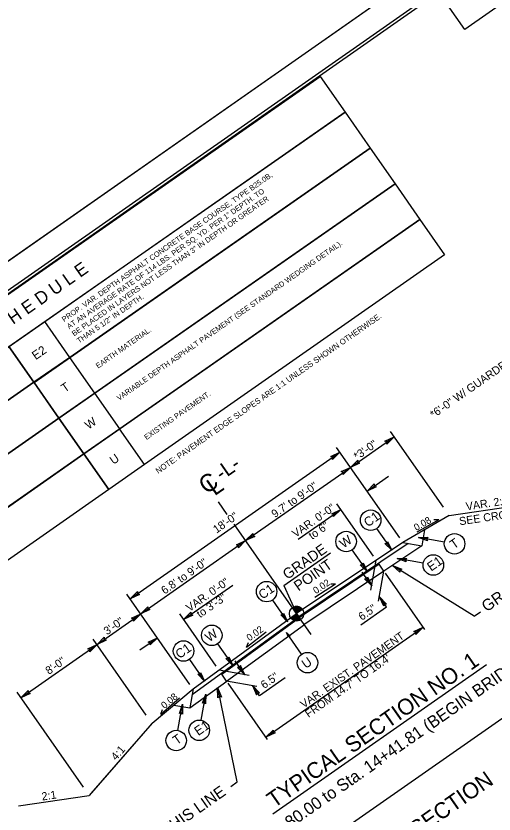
# Model space of a CAD drawing. Extents: x 1033697 to 1037131, y 657437 to 660507.
# Drawn here: x 1035520 to 1035969, y 659179 to 659927 of the extents above; entities that cross this region are included whole.
import ezdxf

# ---------------------------------------------------------------- set-up
doc = ezdxf.new("R2010")
doc.units = 0
for name, color, linetype in [('Default', 7, 'Continuous'), ('Prop Pavement Schedule Description CELL', 7, 'Continuous'), ('Sheet Cutting Line CELL', 7, 'Continuous'), ('Sheet Plot Border Inside CELL', 7, 'Continuous'), ('Sheet Plot Border Outside CELL', 7, 'Continuous'), ('Sheet Title CELL', 7, 'Continuous'), ('Sheet Typical CELL', 7, 'Continuous'), ('Typical Arrow Superelevation CELL', 7, 'Continuous'), ('Typical Grade Point Symbol CELL', 7, 'Continuous'), ('Typical ID Circle CELL', 7, 'Continuous'), ('Typical Pavement Slope CELL', 7, 'Continuous'), ('Typical Pavement Slope Information CELL', 7, 'Continuous'), ('Typical Shoulder Slope CELL', 7, 'Continuous'), ('Typical Shoulder Slope Information CELL', 7, 'Continuous'), ('Typical Slope Point Local CELL', 7, 'Continuous'), ('Typical Terminator CELL', 7, 'Continuous'), ('Typical Text Centerline CELL', 7, 'Continuous'), ('Typical Text General CELL', 7, 'Continuous'), ('Typical Text Grade Point CELL', 7, 'Continuous'), ('Typical Text ID Circle CELL', 7, 'Continuous'), ('Typical Text Label CELL', 7, 'Continuous')]:
    doc.layers.add(name, color=color, linetype=linetype)

msp = doc.modelspace()

# ---------------------------------------------------------------- linework, layer by layer
at = {"layer": 'Default'}
for p, q in [((1035521.13, 658950.73), (1036750.78, 659809.79)), ((1035833.98, 659503.75), (1035874.97, 659532.39)), ((1035921.13, 659466.31), (1035871.41, 659537.48)), ((1035627.28, 659380.55), (1035824.02, 659518)), ((1035880.14, 659437.67), (1035820.93, 659522.42)), ((1035735.61, 659435.03), (1035833.98, 659503.75)), ((1035849.54, 659481.47), (1035869.66, 659495.52)), ((1035718.39, 659459.68), (1035710.09, 659471.55)), ((1035784.94, 659436.33), (1035824.95, 659464.29)), ((1035855.55, 659420.49), (1035821.32, 659469.49)), ((1035796.96, 659347.2), (1035724.8, 659450.5)), ((1035637.23, 659366.3), (1035735.61, 659435.03)), ((1035860.86, 659412.96), (1035785.94, 659362.82)), ((1035853.19, 659388.51), (1035858.19, 659416.71)), ((1035865.35, 659406.46), (1035860.83, 659412.94)), ((1035950.1, 659364.17), (1035873.27, 659411.88)), ((1035865.35, 659406.46), (1035790.33, 659356.25)), ((1035853.91, 659392.6), (1035844.8, 659405.64)), ((1035860.35, 659378.26), (1035865.35, 659406.46)), ((1035903.59, 659351.73), (1035866.71, 659404.52)), ((1035677.39, 659361.2), (1035723.55, 659393.45)), ((1035771.57, 659393.1), (1035783.38, 659366.64)), ((1035683.4, 659300.22), (1035624.19, 659384.97)), ((1035867.69, 659372.88), (1035861.07, 659382.35)), ((1035596.25, 659337.67), (1035637.23, 659366.3)), ((1035707.99, 659317.4), (1035673.76, 659366.4)), ((1035843.63, 659356.07), (1035867.69, 659372.88)), ((1035950.1, 659364.17), (1035955.98, 659368.28)), ((1035713.24, 659309.83), (1035786.09, 659362.92)), ((1035717.79, 659303.37), (1035790.74, 659356.54)), ((1035754.58, 659250.72), (1035902.13, 659353.81)), ((1035636.35, 659332.53), (1035652.8, 659344.02)), ((1035524.86, 659287.8), (1035596.25, 659337.67)), ((1035642.41, 659271.59), (1035592.69, 659342.76)), ((1035734.74, 659309.35), (1035725.73, 659322.24)), ((1035738.83, 659308.63), (1035710.63, 659313.62)), ((1035717.79, 659303.37), (1035713.27, 659309.85)), ((1035772.58, 659306.45), (1035748.53, 659289.64)), ((1035746, 659298.38), (1035717.79, 659303.37)), ((1035756.03, 659248.64), (1035719.15, 659301.43)), ((1035748.53, 659289.64), (1035741.91, 659299.11)), ((1035583.47, 659203.9), (1035521.3, 659292.89)), ((1035727.69, 659208.79), (1035710, 659294.1)), ((1035721.81, 659204.68), (1035727.69, 659208.79))]:
    msp.add_line(p, q, dxfattribs=at)
msp.add_lwpolyline([(1035286.09, 659358.39), (1035252.56, 659334.96), (1035229.13, 659368.49), (1035537.02, 659583.46), (1035560.45, 659549.93), (1035286.09, 659358.39), (1035262.66, 659391.92)], dxfattribs=at)
at = {"layer": 'Prop Pavement Schedule Description CELL'}
for p, q in [((1035583.89, 659516.4), (1035899.2, 659735.97)), ((1035899.2, 659735.97), (1035922.25, 659702.99)), ((1035922.25, 659702.99), (1035640.85, 659506.31)), ((1035640.85, 659506.31), (1035617.42, 659539.84)), ((1035276, 659301.43), (1035583.89, 659516.4)), ((1035583.89, 659516.4), (1035607.33, 659482.87)), ((1035607.32, 659482.87), (1035583.89, 659516.4)), ((1035640.85, 659506.31), (1035607.32, 659482.87)), ((1035607.33, 659482.87), (1035332.97, 659291.32))]:
    msp.add_line(p, q, dxfattribs=at)
msp.add_lwpolyline([(1035182.26, 659435.56), (1035805.49, 659870.11), (1035828.92, 659836.58), (1035205.69, 659402.02)], close=True, dxfattribs=at)
for points in [[(1035570.55, 659606.89), (1035537.02, 659583.46), (1035513.59, 659617), (1035828.87, 659836.64), (1035852.3, 659803.1), (1035570.55, 659606.89), (1035547.13, 659640.43)], [(1035594.02, 659573.29), (1035560.48, 659549.86), (1035537.06, 659583.4), (1035852.33, 659803.03), (1035875.76, 659769.5), (1035594.02, 659573.29), (1035570.59, 659606.82)], [(1035617.45, 659539.75), (1035583.91, 659516.33), (1035560.48, 659549.86), (1035875.77, 659769.5), (1035899.2, 659735.97), (1035617.45, 659539.75), (1035594.02, 659573.29)], [(1035262.66, 659391.92), (1035229.13, 659368.49), (1035205.69, 659402.02), (1035513.58, 659617), (1035537.02, 659583.46), (1035262.66, 659391.92), (1035239.22, 659425.46)], [(1035309.53, 659324.86), (1035276, 659301.43), (1035252.56, 659334.96), (1035560.45, 659549.93), (1035583.89, 659516.4), (1035309.53, 659324.86), (1035286.09, 659358.39)]]:
    msp.add_lwpolyline(points, dxfattribs=at)
at = {"layer": 'Sheet Cutting Line CELL'}
msp.add_line((1036411.33, 660325.1), (1035031.05, 659360.38), dxfattribs=at)
at = {"layer": 'Sheet Plot Border Inside CELL'}
msp.add_lwpolyline([(1036420.5, 660304.13), (1035054.57, 659349.42), (1035659.01, 658484.62), (1037024.95, 659439.32)], close=True, dxfattribs=at)
at = {"layer": 'Sheet Plot Border Outside CELL'}
msp.add_lwpolyline([(1036411.33, 660325.1), (1035031.05, 659360.38), (1035661.22, 658458.77), (1037041.5, 659423.5)], close=True, dxfattribs=at)
at = {"layer": 'Sheet Title CELL'}
msp.add_lwpolyline([(1035916.98, 659949.09), (1036247.75, 660180.27), (1036272.16, 660145.34), (1035941.4, 659914.15)], close=True, dxfattribs=at)
at = {"layer": 'Sheet Typical CELL'}
msp.add_lwpolyline([(1036411.72, 660294.87), (1035182.26, 659435.56), (1035783.78, 658574.94), (1037013.24, 659434.25)], close=True, dxfattribs=at)
at = {"layer": 'Typical Arrow Superelevation CELL'}
for p, q in [((1035916.72, 659454.45), (1035896.34, 659443.14)), ((1035916.72, 659454.45), (1035912.15, 659454.53)), ((1035820.03, 659394.32), (1035800.41, 659381.74)), ((1035820.03, 659394.32), (1035815.46, 659394.1)), ((1035736.43, 659335.34), (1035754.99, 659349.44)), ((1035736.43, 659335.34), (1035738.2, 659339.56)), ((1035655.97, 659272.29), (1035673.6, 659287.53)), ((1035655.97, 659272.29), (1035657.47, 659276.61))]:
    msp.add_line(p, q, dxfattribs=at)
at = {"layer": 'Typical Grade Point Symbol CELL'}
for p, q in [((1035777.88, 659362.8), (1035783.38, 659366.64)), ((1035783.38, 659366.64), (1035779.54, 659372.15)), ((1035788.89, 659370.49), (1035783.38, 659366.64)), ((1035787.21, 659361.13), (1035783.38, 659366.64)), ((1035783.38, 659366.64), (1035787.21, 659361.13))]:
    msp.add_line(p, q, dxfattribs=at)
for points in [[(1035781.98, 659373.2), (1035785.52, 659368.14)], [(1035782.13, 659373.23), (1035785.63, 659368.21)], [(1035782.27, 659373.26), (1035785.74, 659368.29)], [(1035782.42, 659373.29), (1035785.85, 659368.37)], [(1035782.57, 659373.3), (1035785.96, 659368.44)], [(1035782.72, 659373.32), (1035786.07, 659368.52)], [(1035782.88, 659373.33), (1035786.18, 659368.6)], [(1035783.03, 659373.35), (1035786.29, 659368.68)], [(1035783.19, 659373.35), (1035786.4, 659368.75)], [(1035783.35, 659373.35), (1035786.51, 659368.83)], [(1035783.52, 659373.35), (1035786.62, 659368.91)], [(1035783.68, 659373.35), (1035786.73, 659368.98)], [(1035783.85, 659373.34), (1035786.84, 659369.06)], [(1035784.03, 659373.32), (1035786.95, 659369.14)], [(1035784.21, 659373.3), (1035787.06, 659369.21)], [(1035784.39, 659373.28), (1035787.17, 659369.29)], [(1035784.57, 659373.24), (1035787.28, 659369.37)], [(1035784.76, 659373.21), (1035787.39, 659369.44)], [(1035779.59, 659372.18), (1035779.59, 659372.18), (1035783.43, 659366.68)], [(1035779.7, 659372.26), (1035783.54, 659366.75)], [(1035779.81, 659372.32), (1035783.65, 659366.83)], [(1035779.92, 659372.4), (1035783.76, 659366.91)], [(1035780.04, 659372.46), (1035783.87, 659366.98)], [(1035780.16, 659372.53), (1035783.98, 659367.06)], [(1035780.28, 659372.59), (1035784.09, 659367.14)], [(1035780.4, 659372.66), (1035784.2, 659367.21)], [(1035780.52, 659372.72), (1035784.31, 659367.29)], [(1035780.64, 659372.77), (1035784.42, 659367.37)], [(1035780.77, 659372.83), (1035784.53, 659367.45)], [(1035780.9, 659372.88), (1035784.64, 659367.52)], [(1035781.03, 659372.93), (1035784.75, 659367.6)], [(1035781.16, 659372.97), (1035784.86, 659367.68)], [(1035781.29, 659373.02), (1035784.97, 659367.75)], [(1035781.42, 659373.06), (1035785.08, 659367.83)], [(1035781.56, 659373.1), (1035785.19, 659367.91)], [(1035781.7, 659373.15), (1035785.3, 659367.98)], [(1035781.84, 659373.17), (1035785.41, 659368.06)], [(1035782.09, 659365.74), (1035785.82, 659360.39)], [(1035782.2, 659365.81), (1035785.95, 659360.44)], [(1035782.31, 659365.89), (1035786.07, 659360.5)], [(1035782.42, 659365.97), (1035786.2, 659360.55)], [(1035782.53, 659366.04), (1035786.32, 659360.61)], [(1035782.64, 659366.12), (1035786.45, 659360.67)], [(1035782.75, 659366.2), (1035786.57, 659360.73)], [(1035782.86, 659366.27), (1035786.68, 659360.8)], [(1035782.97, 659366.35), (1035786.8, 659360.86)], [(1035783.08, 659366.43), (1035786.91, 659360.94)], [(1035783.19, 659366.51), (1035787.03, 659361)], [(1035783.3, 659366.58), (1035787.14, 659361.08), (1035787.14, 659361.08)], [(1035784.96, 659373.17), (1035787.5, 659369.52)], [(1035785.16, 659373.11), (1035787.61, 659369.6)], [(1035785.37, 659373.05), (1035787.72, 659369.68)], [(1035785.58, 659372.98), (1035787.83, 659369.75)], [(1035785.8, 659372.9), (1035787.94, 659369.83)], [(1035786.03, 659372.8), (1035788.05, 659369.91)], [(1035786.27, 659372.7), (1035788.16, 659369.98)], [(1035786.51, 659372.58), (1035788.27, 659370.06)], [(1035786.79, 659372.42), (1035788.38, 659370.14)], [(1035787.08, 659372.24), (1035788.49, 659370.21)], [(1035787.4, 659372.01), (1035788.6, 659370.29)], [(1035787.77, 659371.71), (1035788.71, 659370.37)], [(1035788.28, 659371.23), (1035788.82, 659370.44)], [(1035777.9, 659362.81), (1035778.32, 659362.21)], [(1035778.01, 659362.89), (1035778.88, 659361.64)], [(1035778.12, 659362.97), (1035779.27, 659361.33)], [(1035778.23, 659363.04), (1035779.61, 659361.08)], [(1035778.34, 659363.12), (1035779.9, 659360.9)], [(1035778.45, 659363.2), (1035780.17, 659360.74)], [(1035778.56, 659363.28), (1035780.43, 659360.61)], [(1035778.67, 659363.35), (1035780.67, 659360.49)], [(1035778.78, 659363.43), (1035780.9, 659360.4)], [(1035778.89, 659363.51), (1035781.12, 659360.31)], [(1035779, 659363.58), (1035781.34, 659360.24)], [(1035779.11, 659363.66), (1035781.54, 659360.19)], [(1035779.22, 659363.74), (1035781.74, 659360.13)], [(1035779.33, 659363.81), (1035781.94, 659360.08)], [(1035779.44, 659363.89), (1035782.14, 659360.04)], [(1035779.55, 659363.97), (1035782.32, 659360)], [(1035779.66, 659364.04), (1035782.5, 659359.98)], [(1035779.77, 659364.12), (1035782.68, 659359.96)], [(1035779.88, 659364.2), (1035782.86, 659359.94)], [(1035779.99, 659364.28), (1035783.03, 659359.93)], [(1035780.1, 659364.35), (1035783.2, 659359.92)], [(1035780.21, 659364.43), (1035783.36, 659359.93)], [(1035780.32, 659364.51), (1035783.52, 659359.93)], [(1035780.43, 659364.58), (1035783.68, 659359.93)], [(1035780.54, 659364.66), (1035783.84, 659359.94)], [(1035780.65, 659364.74), (1035784, 659359.95)], [(1035780.76, 659364.81), (1035784.15, 659359.97)], [(1035780.87, 659364.89), (1035784.3, 659359.99)], [(1035780.99, 659364.97), (1035784.45, 659360.01)], [(1035781.1, 659365.04), (1035784.59, 659360.04)], [(1035781.21, 659365.12), (1035784.73, 659360.07)], [(1035781.31, 659365.2), (1035784.88, 659360.1)], [(1035781.42, 659365.27), (1035785.02, 659360.13)], [(1035781.54, 659365.35), (1035785.16, 659360.17)], [(1035781.65, 659365.43), (1035785.29, 659360.21)], [(1035781.76, 659365.51), (1035785.43, 659360.25)], [(1035781.87, 659365.58), (1035785.56, 659360.3)], [(1035781.98, 659365.66), (1035785.69, 659360.34)]]:
    msp.add_lwpolyline(points, dxfattribs=at)
msp.add_circle((1035783.37, 659366.64), 6.71, dxfattribs=at)
for start, end in [(34.92942, 124.92942), (214.92942, 304.92942)]:
    msp.add_arc((1035783.37, 659366.64), 6.71, start, end, dxfattribs=at)
at = {"layer": 'Typical ID Circle CELL'}
for p, q in [((1035858.46, 659446.35), (1035872.69, 659425.98)), ((1035922.16, 659433.74), (1035897.68, 659438.07)), ((1035835.38, 659426.34), (1035849.62, 659405.97)), ((1035902.21, 659413.85), (1035877.73, 659418.19)), ((1035760.81, 659379.4), (1035775.04, 659359.03)), ((1035788.12, 659328.52), (1035773.88, 659348.89)), ((1035709.34, 659338.39), (1035723.58, 659318.02)), ((1035682.9, 659323.7), (1035697.13, 659303.33)), ((1035693.77, 659266.73), (1035698.12, 659291.2)), ((1035672.14, 659257.13), (1035676.49, 659281.6))]:
    msp.add_line(p, q, dxfattribs=at)
for centre in [(1035852.95, 659454.23), (1035829.88, 659434.22), (1035931.63, 659432.05), (1035911.67, 659412.17), (1035755.3, 659387.28), (1035703.84, 659346.28), (1035677.39, 659331.59), (1035793.62, 659320.64), (1035692.09, 659257.26), (1035670.47, 659247.66)]:
    msp.add_circle(centre, 9.62, dxfattribs=at)
at = {"layer": 'Typical Pavement Slope CELL'}
for p, q in [((1035903.52, 659445.25), (1035900.86, 659430.22)), ((1035883.09, 659433.37), (1035783.38, 659366.64)), ((1035883.09, 659433.37), (1035900.86, 659430.22)), ((1035888.2, 659432.47), (1035785.38, 659363.65)), ((1035900.86, 659430.22), (1035865.35, 659406.46)), ((1035686.42, 659295.98), (1035783.38, 659366.64)), ((1035685.51, 659290.86), (1035785.5, 659363.73)), ((1035683.27, 659278.21), (1035717.84, 659303.41)), ((1035686.42, 659295.98), (1035683.27, 659278.21)), ((1035668.23, 659280.87), (1035683.27, 659278.21))]:
    msp.add_line(p, q, dxfattribs=at)
at = {"layer": 'Typical Shoulder Slope CELL'}
for p, q in [((1035926.5, 659458.62), (1035883.09, 659433.37)), ((1035647.78, 659263.9), (1035686.42, 659295.98))]:
    msp.add_line(p, q, dxfattribs=at)
at = {"layer": 'Typical Slope Point Local CELL'}
for p, q in [((1035926.5, 659458.62), (1036030.06, 659473.86)), ((1035647.78, 659263.9), (1035588.86, 659196.18)), ((1035647.78, 659263.9), (1035590.36, 659197.9)), ((1035647.78, 659263.9), (1035645.08, 659260.79)), ((1035522.48, 659186.41), (1035588.86, 659196.18))]:
    msp.add_line(p, q, dxfattribs=at)
at = {"layer": 'Typical Terminator CELL'}
for p, q in [((1035627.28, 659380.55), (1035634.05, 659387.32)), ((1035627.28, 659380.55), (1035634.05, 659387.32)), ((1035635.89, 659384.6), (1035627.28, 659380.55)), ((1035634.05, 659387.32), (1035634.02, 659385.26)), ((1035634.02, 659385.26), (1035635.89, 659384.6))]:
    msp.add_line(p, q, dxfattribs=at)
for points in [[(1035866.36, 659528.34), (1035874.97, 659532.39), (1035868.19, 659525.62), (1035868.22, 659527.68)], [(1035815.41, 659513.96), (1035824.02, 659518), (1035817.25, 659511.24), (1035817.28, 659513.29)], [(1035842.59, 659507.8), (1035833.98, 659503.75), (1035840.75, 659510.52), (1035840.72, 659508.46)], [(1035825.37, 659499.71), (1035833.98, 659503.75), (1035827.21, 659496.99), (1035827.23, 659499.04)], [(1035858.15, 659485.52), (1035849.54, 659481.47), (1035856.32, 659488.24), (1035856.29, 659486.18)], [(1035816.34, 659460.24), (1035824.95, 659464.29), (1035818.18, 659457.53), (1035818.21, 659459.58)], [(1035744.21, 659439.07), (1035735.61, 659435.03), (1035742.38, 659441.79), (1035742.35, 659439.74)], [(1035727, 659430.98), (1035735.61, 659435.03), (1035728.83, 659428.26), (1035728.86, 659430.32)], [(1035868.85, 659434.16), (1035872.69, 659425.98), (1035866.26, 659432.41), (1035868.21, 659432.39)], [(1035906.19, 659435.01), (1035897.68, 659438.07), (1035906.78, 659438.07), (1035905.38, 659436.71)], [(1035886.23, 659415.12), (1035877.73, 659418.19), (1035886.83, 659418.18), (1035885.43, 659416.82)], [(1035845.78, 659414.14), (1035849.62, 659405.97), (1035843.19, 659412.4), (1035845.14, 659412.37)], [(1035880.38, 659405.57), (1035873.27, 659411.88), (1035882.16, 659408.33), (1035880.26, 659407.54)], [(1035849.87, 659401.2), (1035853.91, 659392.6), (1035847.15, 659399.37), (1035849.2, 659399.34)], [(1035865.12, 659373.74), (1035861.07, 659382.35), (1035867.84, 659375.57), (1035865.79, 659375.6)], [(1035628.63, 659362.26), (1035637.23, 659366.3), (1035630.46, 659359.54), (1035630.49, 659361.59)], [(1035645.84, 659370.35), (1035637.23, 659366.3), (1035644.01, 659373.07), (1035643.98, 659371.02)], [(1035686, 659365.25), (1035677.39, 659361.2), (1035684.17, 659367.97), (1035684.14, 659365.92)], [(1035771.2, 659367.2), (1035775.04, 659359.03), (1035768.62, 659365.46), (1035770.57, 659365.43)], [(1035893.53, 659349.77), (1035902.13, 659353.81), (1035895.36, 659347.05), (1035895.39, 659349.1)], [(1035604.85, 659341.71), (1035596.25, 659337.67), (1035603.02, 659344.43), (1035602.99, 659342.38)], [(1035644.19, 659339.98), (1035652.8, 659344.02), (1035646.03, 659337.26), (1035646.06, 659339.31)], [(1035775.9, 659344.59), (1035773.88, 659348.89), (1035777.26, 659345.5), (1035776.23, 659345.52)], [(1035587.64, 659333.62), (1035596.25, 659337.67), (1035589.47, 659330.9), (1035589.5, 659332.96)], [(1035719.74, 659326.2), (1035723.58, 659318.02), (1035717.15, 659324.45), (1035719.1, 659324.43)], [(1035728.05, 659316.11), (1035734.74, 659309.35), (1035730.71, 659318.03), (1035730.03, 659316.09)], [(1035693.29, 659311.51), (1035697.13, 659303.33), (1035690.71, 659309.76), (1035692.66, 659309.74)], [(1035748.6, 659292.35), (1035741.91, 659299.11), (1035745.94, 659290.43), (1035746.62, 659292.36)], [(1035533.47, 659291.84), (1035524.86, 659287.8), (1035531.63, 659294.56), (1035531.6, 659292.51)], [(1035695.05, 659282.7), (1035698.12, 659291.2), (1035698.11, 659282.11), (1035696.75, 659283.51)], [(1035709.67, 659287.71), (1035709.35, 659297.22), (1035712.9, 659288.33), (1035711.02, 659289.16)], [(1035673.42, 659273.1), (1035676.49, 659281.6), (1035676.48, 659272.51), (1035675.12, 659273.91)], [(1035763.18, 659254.77), (1035754.58, 659250.72), (1035761.35, 659257.49), (1035761.32, 659255.44)]]:
    msp.add_lwpolyline(points, close=True, dxfattribs=at)
at = {"layer": 'Typical Text Grade Point CELL'}
msp.add_line((1035771.57, 659393.1), (1035815.08, 659423.5), dxfattribs=at)
at = {"layer": 'Typical Text Label CELL'}
msp.add_line((1035761.22, 659178.89), (1035961.69, 659318.95), dxfattribs=at)

# ---------------------------------------------------------------- texts
at = {"layer": 'Default'}
for s, rotation, p in [('*6\'-0" W/ GUARDRAIL', 34.93895, (1035911.87, 659549.37)), ('*3\'-0"', 34.93895, (1035840.17, 659510.16)), ('9.7\' to 9\'-0"', 34.93895, (1035763.05, 659456.08)), ('VAR. 0\'-0"', 34.93895, (1035782.42, 659437.61)), (' 18\'-0"', 34.93895, (1035706.01, 659439.98)), ('to 6"', 34.93895, (1035797.98, 659435.67)), ('6.8\' to 9\'-0"', 34.93895, (1035659.63, 659384.37)), ('VAR. 0\'-0"', 34.93895, (1035682.93, 659368.11)), ('to 3\'-3"', 34.93895, (1035692.83, 659362.21)), ('6.5"', 34.93895, (1035844.64, 659359.79)), ('3\'-0"', 34.93895, (1035605.66, 659346.26)), ('VAR. EXIST. PAVEMENT ', 34.93895, (1035790.1, 659277.59)), ("FROM 14.7' TO 16.4'", 34.93895, (1035794.61, 659268.75)), ('8\'-0"', 34.93895, (1035551.02, 659309.09)), ('6.5"', 34.96337, (1035753.03, 659295.81))]:
    msp.add_text(s, height=7.5, rotation=rotation, dxfattribs=at).set_placement(p)
at = {"layer": 'Prop Pavement Schedule Description CELL'}
for s, height, rotation, p in [('PROP. VAR. DEPTH ASPHALT CONCRETE BASE COURSE, TYPE B25.0B,', 5, 34.93895, (1035565.33, 659639.83)), ('AT AN AVERAGE RATE OF 114 LBS. PER SQ. YD. PER 1" DEPTH. TO', 5, 34.93895, (1035570, 659633.14)), ('BE PLACED IN LAYERS NOT LESS THAN 3" IN DEPTH OR GREATER', 5, 34.93895, (1035574.68, 659626.45)), ('VARIABLE DEPTH ASPHALT PAVEMENT (SEE STANDARD WEDGING DETAIL).', 5, 34.93895, (1035616.88, 659566.03)), ('P A V E M E N T   S C H E D U L E', 12, 34.93895, (1035382.9, 659543.35)), ('THAN 5 1/2" IN DEPTH.', 5, 34.93895, (1035579.35, 659619.77)), ('NOTE: PAVEMENT EDGE SLOPES ARE 1:1 UNLESS SHOWN OTHERWISE.', 5.4417, 34.93895, (1035653.57, 659497.49)), ('EARTH MATERIAL.', 5, 34.93895, (1035597.16, 659596.25)), ('E2', 8.167, 34.93895, (1035538.67, 659604.13)), ('T', 8, 34.93895, (1035566.01, 659573.7)), ('EXISTING PAVEMENT.', 5, 34.95116, (1035642.62, 659529.24)), ('W', 8, 34.93895, (1035588.26, 659538.98)), ('U ', 8, 34.95116, (1035611.56, 659506.01)), ('STRUCTURE TYPICAL SECTION', 15, 34.93895, (1035717.16, 659031.37))]:
    msp.add_text(s, height=height, rotation=rotation, dxfattribs=at).set_placement(p)
at = {"layer": 'Typical Pavement Slope Information CELL'}
for rotation, p in [(33.79321, (1035801.54, 659384.73)), (36.08469, (1035739.33, 659340.57))]:
    msp.add_text('0.02', height=6.476, rotation=rotation, dxfattribs=at).set_placement(p)
at = {"layer": 'Typical Shoulder Slope Information CELL'}
for rotation, p in [(30.17748, (1035895.8, 659443.91)), (39.70042, (1035659.51, 659277))]:
    msp.add_text('0.08', height=6.476, rotation=rotation, dxfattribs=at).set_placement(p)
at = {"layer": 'Typical Slope Point Local CELL'}
for s, rotation, p in [('VAR. 2:1 TO 3:1', 8.3739, (1035942.77, 659463.37)), ('SEE CROSS-SECTIONS', 8.28053, (1035936.51, 659449.43)), ('4:1', 48.97519, (1035614.13, 659228.39)), ('2:1', 8.3739, (1035544.78, 659191.39))]:
    msp.add_text(s, height=7.5, rotation=rotation, dxfattribs=at).set_placement(p)
at = {"layer": 'Typical Text Centerline CELL'}
for s, height, rotation, p in [('C', 16.4, 34.93895, (1035698.79, 659477.98)), ('L', 16.41, 34.88585, (1035706.47, 659476.52))]:
    msp.add_text(s, height=height, rotation=rotation, dxfattribs=at).set_placement(p)
at = {"layer": 'Typical Text General CELL'}
for s, height, p in [('-L-', 13.987, (1035713.15, 659490.93)), ('GRADE TO THIS LINE', 10.742, (1035961.72, 659367.69)), ('-L- Sta. 12+80.00 to Sta. 14+41.81 (BEGIN BRIDGE)', 11.3295, (1035712.27, 659119.44)), ('GRADE TO THIS LINE', 10.742, (1035596.95, 659112.73))]:
    msp.add_text(s, height=height, rotation=34.93895, dxfattribs=at).set_placement(p)
at = {"layer": 'Typical Text Grade Point CELL'}
for s, p in [('GRADE', (1035774.71, 659398.15)), ('POINT', (1035785.13, 659387.34))]:
    msp.add_text(s, height=9.787, rotation=34.93895, dxfattribs=at).set_placement(p)
at = {"layer": 'Typical Text ID Circle CELL'}
for s, height, p in [('C1', 8.608, (1035850.26, 659447.4)), ('W', 8.61, (1035827.43, 659427.56)), ('T', 8.61, (1035931.01, 659426.79)), ('E1', 8.608, (1035909.64, 659405.91)), ('C1', 8.608, (1035751.43, 659379.62)), ('W', 8.61, (1035701.39, 659339.61)), ('C1', 8.608, (1035673.52, 659323.93)), ('U', 8.61, (1035792, 659314.67)), ('E1', 8.608, (1035691.18, 659251.79)), ('T', 8.61, (1035670.98, 659243.19))]:
    msp.add_text(s, height=height, rotation=34.93895, dxfattribs=at).set_placement(p)
at = {"layer": 'Typical Text Label CELL'}
msp.add_text('TYPICAL SECTION NO. 1', height=15, rotation=34.93895, dxfattribs=at).set_placement((1035762.24, 659183.95))

doc.saveas('drawing.dxf')
